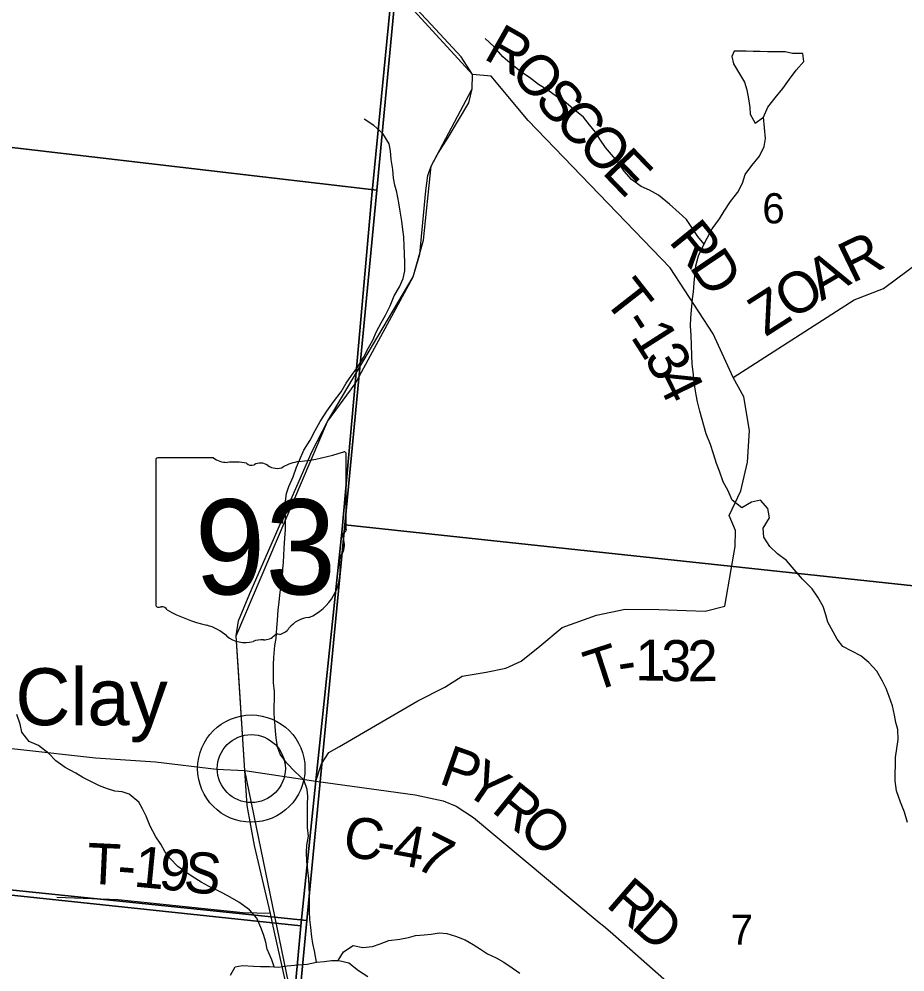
# Model space of a CAD drawing. Extents: x 0 to 42, y 0 to 22.
# Drawn here: x 4.825 to 5.439, y 16.451 to 17.112 of the extents above; entities that cross this region are included whole.
import ezdxf

# ---------------------------------------------------------------- set-up
doc = ezdxf.new("R2010")
doc.units = 0
for name, color, linetype in [('GM_X_County_Road', 7, 'Continuous'), ('GM_X_County_Road_Text', 7, 'Continuous'), ('GM_X_Minor_Lake', 7, 'Continuous'), ('GM_X_Minor_River', 7, 'Continuous'), ('GM_X_Section', 7, 'Continuous'), ('GM_X_Section_Text', 7, 'Continuous'), ('GM_X_State_Location', 7, 'Continuous'), ('GM_X_State_Route', 7, 'Continuous'), ('GM_X_State_Shield', 7, 'Continuous'), ('GM_X_Township_Road', 7, 'Continuous'), ('GM_X_Township_Road_Text', 7, 'Continuous'), ('GM_X_Unincorporated', 7, 'Continuous'), ('GM_X_Unincorporated_Location', 7, 'Continuous'), ('GM_X_Unincorporated_Text', 7, 'Continuous'), ('SH_Data', 7, 'Continuous')]:
    doc.layers.add(name, color=color, linetype=linetype)

msp = doc.modelspace()

# ---------------------------------------------------------------- linework, layer by layer
at = {"layer": 'GM_X_County_Road'}
for points in [[(4.40304, 16.73631), (4.43803, 16.73905), (4.44137, 16.73931), (4.44771, 16.73718), (4.51901, 16.71324), (4.5227, 16.71199), (4.5288, 16.71243), (4.55881, 16.71463), (4.56156, 16.71483), (4.56877, 16.71392), (4.68815, 16.69879), (4.68877, 16.69871), (4.69111, 16.68961), (4.70861, 16.62165), (4.70944, 16.61844), (4.71611, 16.61764), (4.87786, 16.59965), (4.91936, 16.59674), (4.96158, 16.59178), (4.98127, 16.59072)], [(4.98127, 16.59072), (5.03056, 16.58341), (5.09935, 16.574), (5.11864, 16.56977), (5.12763, 16.56607), (5.13979, 16.55814), (5.22669, 16.48533), (5.22982, 16.48317), (5.23441, 16.47912), (5.35743, 16.37064), (5.36063, 16.3678), (5.36629, 16.36788), (5.4806, 16.3695), (5.48196, 16.36953), (5.49053, 16.36957), (5.55017, 16.3699), (5.55134, 16.36991), (5.55871, 16.36516), (5.57543, 16.3544), (5.5758, 16.35416), (5.58201, 16.34697), (5.66325, 16.25295), (5.66548, 16.25033)]]:
    msp.add_lwpolyline(points, dxfattribs=at)
at = {"layer": 'GM_X_Minor_Lake'}
for points in [[(5.34885, 17.05717), (5.35395, 17.06363), (5.35867, 17.07026), (5.3632, 17.07633), (5.36867, 17.08239), (5.36791, 17.08789), (5.36074, 17.08807), (5.35564, 17.08902), (5.35035, 17.08921), (5.34336, 17.08921), (5.33845, 17.08939), (5.33354, 17.08939), (5.32863, 17.08958), (5.32032, 17.08952), (5.31863, 17.08579)], [(5.31863, 17.08579), (5.31995, 17.08086), (5.32335, 17.07499), (5.32751, 17.06817), (5.32903, 17.06286), (5.33035, 17.05642), (5.33111, 17.05055), (5.33149, 17.04581), (5.33489, 17.03975), (5.34074, 17.04373), (5.34376, 17.05074), (5.34885, 17.05717)]]:
    msp.add_lwpolyline(points, dxfattribs=at)
at = {"layer": 'GM_X_Minor_River'}
for points in [[(5.29953, 16.95583), (5.29509, 16.96098), (5.28721, 16.97295), (5.28231, 16.97752), (5.27553, 16.98343), (5.268, 16.98971), (5.26178, 16.99315), (5.25594, 16.99583), (5.24915, 17.0006), (5.24408, 17.00649), (5.2407, 17.01163), (5.23675, 17.01638), (5.23111, 17.02285), (5.22717, 17.02855), (5.22435, 17.03349), (5.22003, 17.03844), (5.2159, 17.04376), (5.20874, 17.04967), (5.20253, 17.05481), (5.19725, 17.05825), (5.19122, 17.06263), (5.18482, 17.06645), (5.17841, 17.07141), (5.17314, 17.07484), (5.16654, 17.07999), (5.15996, 17.0857), (5.15413, 17.09255), (5.14773, 17.09845)], [(5.031, 16.45791), (5.02953, 16.46588), (5.02841, 16.47081), (5.02768, 16.47555), (5.02695, 16.482), (5.02641, 16.48749), (5.02605, 16.49299), (5.0261, 16.50474), (5.02594, 16.51042), (5.02559, 16.51573), (5.02431, 16.52768), (5.02396, 16.53412), (5.02418, 16.53905), (5.02534, 16.54529), (5.0248, 16.55136), (5.02463, 16.55629), (5.02468, 16.56747), (5.02489, 16.57277), (5.02453, 16.5777), (5.0221, 16.58434), (5.01627, 16.58986), (5.01025, 16.59614), (5.00574, 16.60204), (5.00387, 16.60716), (5.00296, 16.61342), (5.0026, 16.61835), (5.00206, 16.6246), (5.00171, 16.6301), (5.00154, 16.63484), (5.00175, 16.64071), (5.00177, 16.64564), (5.00123, 16.65171), (5.00126, 16.65796), (5.0011, 16.66421), (5.00131, 16.66914), (5.0021, 16.67747), (5.00307, 16.68239), (5.00348, 16.68978), (5.00388, 16.69509), (5.00448, 16.70228), (5.00507, 16.70759), (5.00565, 16.71232), (5.00625, 16.718), (5.00741, 16.72539), (5.00762, 16.73032), (5.00802, 16.73524), (5.00823, 16.73998), (5.00844, 16.74509), (5.00904, 16.75191), (5.00944, 16.75797), (5.00947, 16.76479), (5.00931, 16.77124), (5.00953, 16.77749), (5.01012, 16.78279), (5.01184, 16.78771), (5.0147, 16.79452), (5.01719, 16.80114), (5.0191, 16.80606), (5.02215, 16.81287), (5.02653, 16.81986), (5.02996, 16.82648), (5.03339, 16.8329), (5.03814, 16.83989), (5.04271, 16.84651), (5.04803, 16.85349), (5.05145, 16.85935), (5.05526, 16.86464), (5.05963, 16.87069), (5.06344, 16.87711), (5.06706, 16.88392), (5.06991, 16.88921), (5.0724, 16.89526), (5.07582, 16.90112), (5.07868, 16.90661), (5.08192, 16.91303), (5.08478, 16.91984), (5.0884, 16.92627), (5.09107, 16.93194), (5.09204, 16.93724), (5.09206, 16.94236), (5.09191, 16.94956), (5.09174, 16.95449), (5.09139, 16.96075), (5.09065, 16.96587), (5.09011, 16.97174), (5.08901, 16.97857), (5.0879, 16.98445), (5.08661, 16.99184), (5.08512, 16.99659), (5.08438, 17.00152), (5.08384, 17.00759), (5.08274, 17.01441), (5.0822, 17.02048), (5.08128, 17.02541), (5.07696, 17.03244), (5.07075, 17.03796), (5.06396, 17.04235)], [(5.39176, 16.68199), (5.38895, 16.68693), (5.3852, 16.69377), (5.3839, 16.6987), (5.38203, 16.70459), (5.37828, 16.71104), (5.37434, 16.71675), (5.36757, 16.72341), (5.36193, 16.73026), (5.35666, 16.73634), (5.35026, 16.74111), (5.34499, 16.74606), (5.34086, 16.75252), (5.34032, 16.75896), (5.34489, 16.76596), (5.34359, 16.7724), (5.33852, 16.7783), (5.33227, 16.77681), (5.32564, 16.77305), (5.31905, 16.7782), (5.31625, 16.78465), (5.31268, 16.79092), (5.31007, 16.79832), (5.3082, 16.80364), (5.30596, 16.81047), (5.30391, 16.81692), (5.30092, 16.82433), (5.29645, 16.83988), (5.29497, 16.84633), (5.29405, 16.85126), (5.29276, 16.85828), (5.29222, 16.8651), (5.29112, 16.87269), (5.29095, 16.87856), (5.2908, 16.88596), (5.29045, 16.8924), (5.2901, 16.89903), (5.29031, 16.90472), (5.29071, 16.91002), (5.2915, 16.91779), (5.29209, 16.92271), (5.29268, 16.92896), (5.29308, 16.93389), (5.29368, 16.94071), (5.2956, 16.94771), (5.29846, 16.95357), (5.30151, 16.96), (5.30513, 16.96643), (5.31007, 16.97323), (5.3135, 16.97871), (5.31768, 16.98532), (5.32281, 16.99193), (5.32605, 16.99798), (5.32797, 17.00404), (5.33253, 17.01027), (5.33785, 17.01688), (5.34109, 17.0235), (5.34206, 17.02899), (5.34074, 17.04373)], [(5.44053, 16.55482), (5.43829, 16.56184), (5.43568, 16.56886), (5.43288, 16.57665), (5.43196, 16.58366), (5.43179, 16.5884), (5.43201, 16.59503), (5.43222, 16.59977), (5.433, 16.60602), (5.43398, 16.61226), (5.43363, 16.61928), (5.43233, 16.62402), (5.43141, 16.62914), (5.42992, 16.63578), (5.42768, 16.64204), (5.42563, 16.64773), (5.42319, 16.65267), (5.41907, 16.6597), (5.41361, 16.66579), (5.40815, 16.67036), (5.40174, 16.67361), (5.39552, 16.67686), (5.39176, 16.68199)], [(5.00167, 16.45463), (5.00002, 16.45957), (4.99684, 16.46697), (4.99573, 16.47171), (4.99424, 16.47703), (4.99237, 16.48196), (4.98956, 16.48842), (4.98449, 16.49412), (4.97714, 16.49965), (4.9696, 16.50385), (4.9647, 16.50653), (4.95603, 16.51074), (4.95112, 16.51341), (4.94472, 16.51742), (4.93982, 16.52085), (4.93492, 16.52428), (4.92928, 16.52999), (4.9259, 16.53475), (4.92308, 16.53969), (4.9197, 16.54482), (4.91577, 16.55222), (4.91296, 16.55925), (4.91034, 16.56419), (4.9079, 16.56893), (4.90112, 16.57446), (4.89622, 16.576), (4.89131, 16.57659), (4.88621, 16.57813), (4.88055, 16.58024), (4.87452, 16.5831), (4.86905, 16.58597), (4.86415, 16.58903), (4.8568, 16.59285), (4.85039, 16.59742), (4.8455, 16.60256), (4.83835, 16.60809), (4.83193, 16.61096), (4.82686, 16.61743), (4.82556, 16.62293), (4.82332, 16.62957)], [(5.04594, 16.45898), (5.04955, 16.46503), (5.05637, 16.46955), (5.06298, 16.468), (5.06979, 16.46873), (5.07509, 16.4706), (5.08095, 16.47304), (5.08871, 16.47395), (5.09457, 16.47506), (5.09949, 16.47637), (5.10554, 16.47691), (5.11045, 16.47746), (5.11594, 16.47819), (5.12122, 16.47779), (5.12726, 16.47606), (5.13387, 16.47337), (5.13952, 16.47013), (5.14461, 16.46688), (5.14951, 16.46383), (5.15535, 16.46096), (5.16082, 16.45791), (5.16647, 16.45409), (5.17175, 16.45028)], [(4.97144, 16.44889), (4.97468, 16.45475), (4.9796, 16.45568), (4.98734, 16.45526), (4.99225, 16.45486), (4.99849, 16.45484), (5.00472, 16.45443), (5.01058, 16.45535), (5.01815, 16.45608), (5.02457, 16.45662), (5.031, 16.45791), (5.0363, 16.45846), (5.0414, 16.459), (5.0465, 16.45898), (5.0533, 16.45744), (5.06008, 16.4521), (5.06648, 16.44809)]]:
    msp.add_lwpolyline(points, dxfattribs=at)
at = {"layer": 'GM_X_Section'}
for points in [[(5.12031, 17.49685), (5.09837, 17.26445), (5.07281, 16.99321), (4.55914, 17.05322), (4.61913, 17.54396)], [(5.09837, 17.26445), (5.63895, 17.21787), (5.59959, 16.70229), (5.05068, 16.76119), (5.07281, 16.99321)], [(4.55914, 17.05322), (5.07281, 16.99321), (5.05068, 16.76119), (5.02417, 16.48692), (4.53436, 16.53744), (4.51258, 16.53954)], [(5.59959, 16.70229), (5.55229, 16.21494), (5.00319, 16.26475), (5.02417, 16.48692), (5.05068, 16.76119)], [(5.02417, 16.48692), (5.00319, 16.26475), (4.97837, 15.9812), (4.48155, 16.02605), (4.53436, 16.53744)]]:
    msp.add_lwpolyline(points, close=True, dxfattribs=at)
at = {"layer": 'GM_X_State_Route'}
for points in [[(4.99899, 16.49168), (4.98797, 16.53887), (4.98286, 16.56666), (4.98127, 16.59072), (4.97684, 16.65998), (4.97531, 16.68427), (4.97699, 16.6945), (4.98469, 16.71351), (5.02784, 16.81227), (5.03849, 16.83283), (5.05781, 16.859), (5.09782, 16.93311), (5.10256, 16.94885), (5.10663, 16.99268), (5.10817, 17.00333), (5.11033, 17.00981), (5.11527, 17.01877), (5.12206, 17.02972), (5.13656, 17.05364), (5.13888, 17.06337), (5.13903, 17.0734), (5.13117, 17.08554), (5.10737, 17.1112), (5.08362, 17.13651)], [(5.0412, 16.26377), (5.04296, 16.27481), (5.04356, 16.28784), (5.04114, 16.30177), (5.02721, 16.36598), (5.01457, 16.42213), (5.00955, 16.44445), (5.00049, 16.48494), (4.99899, 16.49168)]]:
    msp.add_lwpolyline(points, dxfattribs=at)
at = {"layer": 'GM_X_State_Shield'}
for p, q in [((5.05147, 16.7578), (5.05147, 16.81015)), ((4.91964, 16.80595), (4.91964, 16.70589)), ((4.95954, 16.80767), (4.92093, 16.80767)), ((5.05146, 16.75782), (5.05147, 16.7578))]:
    msp.add_line(p, q, dxfattribs=at)
for centre, radius, start, end in [((5.00451, 16.94408), 0.13981, 275.84447, 288.90645), ((5.05001, 16.81036), 0.00147, 351.86209, 97.738), ((4.92115, 16.80616), 0.00153, 98.1301, 188.1301), ((4.96874, 16.81928), 0.01481, 231.61951, 271.11188), ((4.97365, 16.75149), 0.05318, 80.48669, 94.98827), ((4.98572, 16.80668), 0.00427, 219.79206, 297.10237), ((4.992, 16.79511), 0.00889, 54.46668, 119.14113), ((5.00346, 16.81098), 0.01069, 233.85621, 294.82819), ((5.02234, 16.77711), 0.02813, 97.34618, 120.76885), ((5.05113, 16.75396), 0.00227, 107.94398, 210.33697), ((5.0499, 16.7576), 0.00157, 289.60381, 7.73413), ((5.03668, 16.74735), 0.01363, 340.03296, 23.64957), ((5.05673, 16.7359), 0.00992, 136.8065, 186.92959), ((5.01234, 16.72924), 0.03497, 292.30889, 8.98584), ((4.92116, 16.70567), 0.00154, 171.95839, 258.30661), ((4.92139, 16.7159), 0.01176, 267.33899, 280.60386), ((4.9238, 16.70011), 0.00424, 29.74838, 93.27175), ((4.97733, 16.79001), 0.10096, 240.41292, 257.1985), ((5.02709, 16.67779), 0.01915, 94.40312, 142.57675), ((4.94723, 16.66093), 0.03159, 47.18416, 75.83597), ((5.00282, 16.69619), 0.0113, 282.87319, 323.27711), ((4.98139, 16.69962), 0.02004, 230.70037, 286.29184), ((4.99444, 16.69212), 0.01068, 268.77702, 315.54927), ((5.0041, 16.68243), 0.00301, 65.75173, 132.64842), ((4.99298, 16.66502), 0.01647, 85.69512, 111.20995)]:
    msp.add_arc(centre, radius, start, end, dxfattribs=at)
at = {"layer": 'GM_X_Township_Road'}
for points in [[(2.1647, 16.77107), (2.57825, 16.72962), (2.68525, 16.71838), (2.97417, 16.68996), (3.03136, 16.68495), (3.42177, 16.64721), (3.49843, 16.6396), (3.92254, 16.6011), (3.99035, 16.5952), (4.03378, 16.59046), (4.40465, 16.549), (4.51047, 16.53717), (5.00039, 16.4852), (5.02016, 16.4831), (5.03045, 16.58367), (5.04866, 16.75825), (5.05771, 16.85926), (5.06939, 16.98984), (5.08351, 17.13677), (5.09562, 17.26276), (5.1195, 17.49729), (5.12853, 17.5887), (5.14624, 17.76794), (5.1674, 18.00102)], [(6.64854, 17.1358), (6.05163, 17.18401), (5.92492, 17.19421), (5.76905, 17.20333), (5.50003, 17.22995), (5.09562, 17.26276), (5.08351, 17.13677), (5.06939, 16.98984), (5.05771, 16.85926), (5.04866, 16.75825), (5.03045, 16.58367), (5.02016, 16.4831), (5.01446, 16.42239), (4.99947, 16.26251), (4.97611, 15.98164), (4.96357, 15.8483)], [(5.31959, 16.86341), (5.30571, 16.89359), (5.2759, 16.93943), (5.1777, 17.04142), (5.15199, 17.07216), (5.13903, 17.0734)], [(5.03056, 16.58341), (5.03444, 16.59556), (5.03958, 16.60327), (5.04678, 16.60751), (5.10121, 16.63902), (5.1199, 16.64859), (5.13197, 16.65623), (5.14841, 16.65896), (5.16202, 16.66187), (5.17278, 16.66666), (5.1856, 16.67715), (5.20125, 16.68993), (5.22485, 16.69857), (5.24489, 16.70265), (5.26815, 16.70257), (5.28707, 16.70172), (5.30012, 16.7014), (5.31391, 16.70488), (5.31816, 16.73011), (5.32093, 16.74623), (5.32126, 16.75723), (5.31686, 16.76763), (5.32492, 16.78473), (5.32957, 16.80465), (5.33099, 16.82665), (5.32692, 16.84994), (5.31959, 16.86341), (5.40343, 16.91723), (5.42382, 16.92491), (5.4489, 16.94379)], [(4.96357, 15.8483), (4.97611, 15.98164), (4.99947, 16.26251), (5.01446, 16.42239), (5.02016, 16.4831), (5.00039, 16.4852), (4.51047, 16.53717), (4.40465, 16.549), (4.03378, 16.59046), (3.99035, 16.5952), (3.92254, 16.6011), (3.49843, 16.6396), (3.42177, 16.64721), (3.03136, 16.68495), (2.97417, 16.68996), (2.68525, 16.71838), (2.57825, 16.72962), (2.1647, 16.77107), (2.1, 16.7767), (2.1, 14.1)], [(4.99899, 16.49168), (4.98009, 16.49223), (4.89343, 16.50127), (4.85105, 16.50269)]]:
    msp.add_lwpolyline(points, dxfattribs=at)
at = {"layer": 'GM_X_Unincorporated'}
for radius in [0.0372, 0.02358]:
    msp.add_circle((4.98577, 16.59215), radius, dxfattribs=at)
at = {"layer": 'GM_X_Unincorporated_Location'}
msp.add_line((4.98577, 16.59215), (4.98577, 16.59215), dxfattribs=at)
at = {"layer": 'SH_Data'}
msp.add_lwpolyline([(4.92613, 15.41609), (4.96368, 15.84804), (4.97622, 15.98138), (4.98336, 16.0136), (5.02488, 16.15967), (5.04356, 16.28784), (4.98127, 16.59072), (4.97531, 16.68427), (5.03849, 16.83283), (5.09782, 16.93311), (5.10516, 16.95862), (5.11033, 17.00981), (5.13888, 17.06337), (5.13903, 17.0734), (5.07075, 17.14821), (4.98022, 17.1883), (4.91553, 17.26618)], dxfattribs=at)

# ---------------------------------------------------------------- texts
at = {"layer": 'GM_X_County_Road_Text'}
for s, rotation, p in [('P', 340.653, (5.11486, 16.58211)), ('Y', 325.66634, (5.13119, 16.57664)), ('R', 320.91353, (5.15134, 16.56291)), ('O', 320.6296, (5.16942, 16.54823)), ('C', 351.31408, (5.0482, 16.53177)), ('4', 349.56064, (5.08257, 16.52648)), ('7', 333.7887, (5.09782, 16.52396)), ('-', 351.09717, (5.07124, 16.52825)), ('R', 319.16238, (5.23068, 16.49715)), ('D', 318.6149, (5.24815, 16.48206))]:
    msp.add_text(s, height=0.02841, rotation=rotation, dxfattribs=at).set_placement(p)
at = {"layer": 'GM_X_Section_Text'}
for s, p in [('6', (5.3398, 16.97018)), ('7', (5.31793, 16.47002))]:
    msp.add_text(s, height=0.02093, rotation=0.00001, dxfattribs=at).set_placement(p)
at = {"layer": 'GM_X_State_Location'}
for s, p in [('s', (4.98407, 16.74926)), ('r', (4.98406, 16.74926))]:
    msp.add_text(s, height=0.0000947, dxfattribs=at).set_placement(p)
msp.add_text('93', height=0.0000947, rotation=0.00001, dxfattribs=at).set_placement((4.96022, 16.74237))
at = {"layer": 'GM_X_State_Shield'}
msp.add_text('93', height=0.065918, dxfattribs=at).set_placement((4.94646, 16.71294))
at = {"layer": 'GM_X_Township_Road_Text'}
for s, rotation, p in [('R', 330.49959, (5.14588, 17.08471)), ('O', 310.26032, (5.16416, 17.0749)), ('S', 312.26338, (5.18103, 17.05501)), ('C', 313.77923, (5.19448, 17.04022)), ('O', 313.95042, (5.21069, 17.02331)), ('E', 313.95452, (5.22804, 17.00531)), ('R', 309.06395, (5.27439, 16.95765)), ('R', 25.77781, (5.40187, 16.92835)), ('D', 303.98811, (5.2887, 16.94006)), ('A', 30.39462, (5.38084, 16.91599)), ('T', 308.14375, (5.22906, 16.91753)), ('O', 32.5483, (5.36001, 16.90269)), ('Z', 32.58459, (5.34211, 16.89124)), ('-', 303.12499, (5.2418, 16.90135)), ('1', 302.5151, (5.24813, 16.89165)), ('3', 299.27045, (5.25732, 16.87726)), ('4', 296.13683, (5.26569, 16.86236)), ('T', 18.00263, (5.22238, 16.64529)), ('1', 359.8699, (5.25178, 16.65325)), ('3', 357.94921, (5.26903, 16.65321)), ('2', 0.96489, (5.28815, 16.65257)), ('-', 8.66663, (5.2414, 16.65158)), ('T', 357.28348, (4.87135, 16.51236)), ('1', 354.44698, (4.90369, 16.51047)), ('9', 354.05909, (4.92092, 16.5088)), ('S', 354.06083, (4.93819, 16.507)), ('-', 355.47257, (4.8923, 16.51137))]:
    msp.add_text(s, height=0.02841, rotation=rotation, dxfattribs=at).set_placement(p)
at = {"layer": 'GM_X_Unincorporated_Text'}
msp.add_text('Clay', height=0.039489, rotation=0.00001, dxfattribs=at).set_placement((4.82231, 16.62221))

doc.saveas('drawing.dxf')
